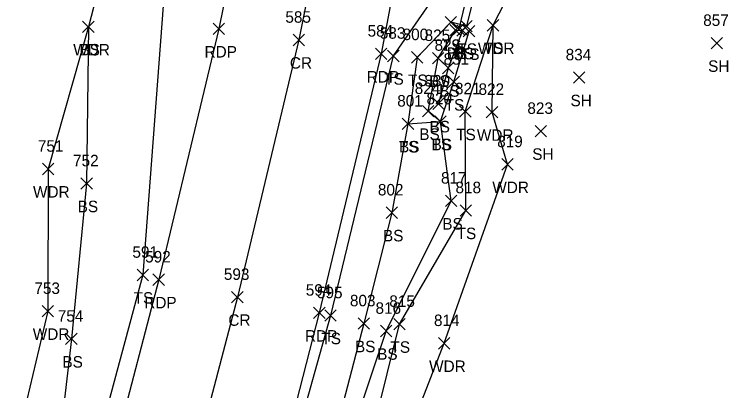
# Model space of a CAD drawing. Extents: x 1638705 to 1644019, y 630225 to 637423.
# Drawn here: x 1643815.9 to 1643939.5, y 636901.8 to 636967.4 of the extents above; entities that cross this region are included whole.
import ezdxf

# ---------------------------------------------------------------- set-up
doc = ezdxf.new("R2010")
doc.units = 0
for name, color, linetype in [('D_A', 7, 'Continuous'), ('D_TIC', 7, 'Continuous'), ('DCP', 7, 'Continuous'), ('L_A', 7, 'Continuous'), ('L_I', 7, 'Continuous'), ('L_TIC', 7, 'Continuous'), ('LAWA', 7, 'Continuous'), ('LELB', 7, 'Continuous'), ('P_A', 7, 'Continuous'), ('P_I', 7, 'Continuous'), ('P_TIC', 7, 'Continuous'), ('PET', 7, 'Continuous'), ('PRC', 7, 'Continuous')]:
    doc.layers.add(name, color=color, linetype=linetype)

msp = doc.modelspace()

# ---------------------------------------------------------------- linework, layer by layer
at = {"layer": 'D_TIC'}
for points in [[(1643892.43, 636963.79), (1643894.43, 636965.79)], [(1643894.43, 636963.79), (1643892.43, 636965.79)]]:
    msp.add_lwpolyline(points, dxfattribs=at)
at = {"layer": 'DCP'}
msp.add_lwpolyline([(1643899.78, 636991.21), (1643893.43, 636964.79)], dxfattribs=at)
at = {"layer": 'L_TIC'}
for points in [[(1643891.04, 636964.97), (1643893.04, 636966.97)], [(1643893.04, 636964.97), (1643891.04, 636966.97)], [(1643827.82, 636964.18), (1643829.82, 636966.18)], [(1643829.82, 636964.18), (1643827.82, 636966.18)], [(1643827.82, 636964.18), (1643829.82, 636966.18)], [(1643829.82, 636964.18), (1643827.82, 636966.18)], [(1643891.86, 636963.57), (1643893.86, 636965.57)], [(1643893.86, 636963.57), (1643891.86, 636965.57)], [(1643893.09, 636963.51), (1643895.09, 636965.51)], [(1643895.09, 636963.51), (1643893.09, 636965.51)], [(1643893.77, 636964.28), (1643895.77, 636966.28)], [(1643895.77, 636964.28), (1643893.77, 636966.28)], [(1643894.22, 636963.41), (1643896.22, 636965.41)], [(1643896.22, 636963.41), (1643894.22, 636965.41)], [(1643898.4, 636964.43), (1643900.4, 636966.43)], [(1643900.4, 636964.43), (1643898.4, 636966.43)], [(1643898.4, 636964.43), (1643900.4, 636966.43)], [(1643900.4, 636964.43), (1643898.4, 636966.43)], [(1643937.43, 636961.32), (1643939.43, 636963.32)], [(1643939.43, 636961.32), (1643937.43, 636963.32)], [(1643881.01, 636959.09), (1643883.01, 636961.09)], [(1643883.01, 636959.09), (1643881.01, 636961.09)], [(1643885.16, 636958.85), (1643887.16, 636960.85)], [(1643887.16, 636958.85), (1643885.16, 636960.85)], [(1643888.82, 636958.7), (1643890.82, 636960.7)], [(1643890.82, 636958.7), (1643888.82, 636960.7)], [(1643890.57, 636956.99), (1643892.57, 636958.99)], [(1643892.57, 636956.99), (1643890.57, 636958.99)], [(1643913.43, 636955.33), (1643915.43, 636957.33)], [(1643915.43, 636955.33), (1643913.43, 636957.33)], [(1643891.56, 636954.57), (1643893.56, 636956.57)], [(1643893.56, 636954.57), (1643891.56, 636956.57)], [(1643888.88, 636950.78), (1643890.88, 636952.78)], [(1643890.88, 636950.78), (1643888.88, 636952.78)], [(1643887.1, 636949.47), (1643889.1, 636951.47)], [(1643889.1, 636949.47), (1643887.1, 636951.47)], [(1643893.56, 636949.41), (1643895.56, 636951.41)], [(1643895.56, 636949.41), (1643893.56, 636951.41)], [(1643898.23, 636949.31), (1643900.23, 636951.31)], [(1643900.23, 636949.31), (1643898.23, 636951.31)], [(1643883.56, 636947.28), (1643885.56, 636949.28)], [(1643885.56, 636947.28), (1643883.56, 636949.28)], [(1643883.56, 636947.28), (1643885.56, 636949.28)], [(1643885.56, 636947.28), (1643883.56, 636949.28)], [(1643889.24, 636947.66), (1643891.24, 636949.66)], [(1643891.24, 636947.66), (1643889.24, 636949.66)], [(1643889.24, 636947.66), (1643891.24, 636949.66)], [(1643891.24, 636947.66), (1643889.24, 636949.66)], [(1643906.75, 636946), (1643908.75, 636948)], [(1643908.75, 636946), (1643906.75, 636948)], [(1643900.92, 636940.2), (1643902.92, 636942.2)], [(1643902.92, 636940.2), (1643900.92, 636942.2)], [(1643820.8, 636939.41), (1643822.8, 636941.41)], [(1643822.8, 636939.41), (1643820.8, 636941.41)], [(1643827.51, 636936.87), (1643829.51, 636938.87)], [(1643829.51, 636936.87), (1643827.51, 636938.87)], [(1643891.11, 636933.85), (1643893.11, 636935.85)], [(1643893.11, 636933.85), (1643891.11, 636935.85)], [(1643880.76, 636931.79), (1643882.76, 636933.79)], [(1643882.76, 636931.79), (1643880.76, 636933.79)], [(1643893.64, 636932.18), (1643895.64, 636934.18)], [(1643895.64, 636932.18), (1643893.64, 636934.18)], [(1643837.3, 636920.94), (1643839.3, 636922.94)], [(1643839.3, 636920.94), (1643837.3, 636922.94)], [(1643820.76, 636914.63), (1643822.76, 636916.63)], [(1643822.76, 636914.63), (1643820.76, 636916.63)], [(1643870.05, 636913.88), (1643872.05, 636915.88)], [(1643872.05, 636913.88), (1643870.05, 636915.88)], [(1643875.88, 636912.48), (1643877.88, 636914.48)], [(1643877.88, 636912.48), (1643875.88, 636914.48)], [(1643882.1, 636912.38), (1643884.1, 636914.38)], [(1643884.1, 636912.38), (1643882.1, 636914.38)], [(1643879.75, 636911.17), (1643881.75, 636913.17)], [(1643881.75, 636911.17), (1643879.75, 636913.17)], [(1643824.85, 636909.8), (1643826.85, 636911.8)], [(1643826.85, 636909.8), (1643824.85, 636911.8)], [(1643889.89, 636909.04), (1643891.89, 636911.04)], [(1643891.89, 636909.04), (1643889.89, 636911.04)]]:
    msp.add_lwpolyline(points, dxfattribs=at)
at = {"layer": 'LAWA'}
for points in [[(1643865.64, 637303.77), (1643862.82, 637270.27), (1643861.25, 637253.7), (1643870.99, 637241.9), (1643867.11, 637203.42), (1643864.21, 637161.34), (1643862.97, 637130.77), (1643854.22, 637098.04), (1643864.2, 637092.72), (1643858.24, 637074.74), (1643852.38, 637053.09), (1643849.03, 637029.11), (1643850.77, 637013.92), (1643837.37, 636980.48), (1643832.85, 636980.73), (1643828.82, 636965.18), (1643821.8, 636940.41), (1643821.76, 636915.63), (1643813.91, 636882.55), (1643810.67, 636866.31)], [(1643866.42, 636846.23), (1643870.33, 636868.74), (1643881.97, 636887.15), (1643890.89, 636910.04), (1643901.92, 636941.2), (1643899.23, 636950.31), (1643899.4, 636965.43), (1643906.72, 636979.6), (1643908.72, 636993.2), (1643928.1, 637008.65), (1643931.38, 637033.38), (1643927.97, 637042.71)]]:
    msp.add_lwpolyline(points, dxfattribs=at)
at = {"layer": 'LELB'}
for points in [[(1643917.29, 637304.48), (1643919.24, 637262.47), (1643916.89, 637218.55), (1643914.08, 637180.95), (1643910.3, 637135.87), (1643913.16, 637114.46), (1643911.21, 637098.67), (1643904.37, 637090.61), (1643898.51, 637049.58), (1643891.41, 637000.85), (1643892.59, 636975.41), (1643882.01, 636960.09), (1643871.05, 636914.88), (1643861.76, 636881.64), (1643855.17, 636855.93)], [(1643881.31, 637303.51), (1643880.47, 637260.36), (1643877.75, 637219.48), (1643872.16, 637183.49), (1643871.11, 637167.53), (1643875.06, 637139.18), (1643871.64, 637093.85), (1643865.67, 637053.39), (1643855.97, 637011.76), (1643842.4, 636975.8), (1643838.3, 636921.94), (1643830.67, 636893.45), (1643822.68, 636863.82)], [(1643913.32, 637074.89), (1643909.21, 637064.03), (1643906.43, 637047.21), (1643907.23, 637022.8), (1643903.37, 637008.28), (1643895.6, 636995.38), (1643898.69, 636989.86), (1643900.72, 636989.28), (1643894.77, 636965.28), (1643892.04, 636965.97), (1643886.16, 636959.85), (1643884.56, 636948.28), (1643890.24, 636948.66), (1643892.56, 636955.57), (1643895.22, 636964.41)], [(1643870.33, 636868.74), (1643876.6, 636887.17), (1643883.1, 636913.38), (1643894.64, 636933.18), (1643894.56, 636950.41), (1643899.4, 636965.43)], [(1643828.82, 636965.18), (1643828.51, 636937.87), (1643825.85, 636910.8), (1643822.97, 636885.89), (1643815.74, 636865.22)], [(1643860.83, 636847.55), (1643868.13, 636873.63), (1643872.66, 636888.12), (1643880.75, 636912.17), (1643892.11, 636934.85), (1643890.24, 636948.66), (1643888.1, 636950.47), (1643889.82, 636959.7), (1643892.86, 636964.57), (1643894.09, 636964.51), (1643891.57, 636957.99), (1643889.88, 636951.78)], [(1643884.56, 636948.28), (1643881.76, 636932.79), (1643876.88, 636913.48), (1643870.82, 636890.34), (1643863.68, 636867.43), (1643857.57, 636848.74)]]:
    msp.add_lwpolyline(points, dxfattribs=at)
at = {"layer": 'P_TIC'}
for points in [[(1643850.59, 636963.82), (1643852.59, 636965.82)], [(1643852.59, 636963.82), (1643850.59, 636965.82)], [(1643864.54, 636961.88), (1643866.54, 636963.88)], [(1643866.54, 636961.88), (1643864.54, 636963.88)], [(1643878.88, 636959.46), (1643880.88, 636961.46)], [(1643880.88, 636959.46), (1643878.88, 636961.46)], [(1643840.08, 636920.12), (1643842.08, 636922.12)], [(1643842.08, 636920.12), (1643840.08, 636922.12)], [(1643853.81, 636917.08), (1643855.81, 636919.08)], [(1643855.81, 636917.08), (1643853.81, 636919.08)], [(1643868.1, 636914.33), (1643870.1, 636916.33)], [(1643870.1, 636914.33), (1643868.1, 636916.33)]]:
    msp.add_lwpolyline(points, dxfattribs=at)
at = {"layer": 'PET'}
for points in [[(1643915.42, 637304.49), (1643914.6, 637262.42), (1643913.48, 637219.01), (1643911.31, 637181.13), (1643907.88, 637136.04), (1643902.19, 637091.19), (1643896.2, 637050.09), (1643887.54, 637001.12), (1643879.88, 636960.46), (1643869.1, 636915.33), (1643860.5, 636882.08), (1643852.88, 636856.28)], [(1643886.09, 637303.33), (1643885.33, 637260.95), (1643884.29, 637219.34), (1643882.65, 637181.95), (1643878.66, 637138.56), (1643873.79, 637093.66), (1643868.41, 637053.44), (1643859.66, 637004.66), (1643851.59, 636964.82), (1643841.08, 636921.12), (1643833.58, 636892.49), (1643824.77, 636863.46)]]:
    msp.add_lwpolyline(points, dxfattribs=at)
at = {"layer": 'PRC'}
msp.add_lwpolyline([(1643901.07, 637302.92), (1643900.04, 637261.19), (1643898.85, 637218.55), (1643896.7, 637181.82), (1643893.13, 637137.2), (1643887.51, 637091.29), (1643882.08, 637051.36), (1643873.69, 637003.61), (1643865.54, 636962.88), (1643854.81, 636918.08), (1643846.66, 636887.04), (1643838.69, 636859.97)], dxfattribs=at)

# ---------------------------------------------------------------- texts
at = {"layer": 'D_A'}
msp.add_text('P', height=2, dxfattribs=at).set_placement((1643892.8, 636959.79))
at = {"layer": 'L_A'}
for s, p in [('TS', (1643890.45, 636960.97)), ('WDR', (1643826.18, 636960.18)), ('BS', (1643827.26, 636960.18)), ('BS', (1643891.3, 636959.57)), ('BS', (1643892.53, 636959.51)), ('TS', (1643893.18, 636960.28)), ('WDR', (1643896.76, 636960.43)), ('TS', (1643897.81, 636960.43)), ('TS', (1643893.63, 636959.41)), ('SH', (1643936.92, 636957.32)), ('TS', (1643880.42, 636955.09)), ('TS', (1643884.57, 636954.85)), ('BS', (1643888.26, 636954.7)), ('BS', (1643890.01, 636952.99)), ('SH', (1643912.92, 636951.33)), ('TS', (1643890.97, 636950.57)), ('BS', (1643888.32, 636946.78)), ('BS', (1643886.54, 636945.47)), ('TS', (1643892.97, 636945.41)), ('WDR', (1643896.59, 636945.31)), ('TS', (1643888.65, 636943.66)), ('BS', (1643888.68, 636943.66)), ('TS', (1643882.97, 636943.28)), ('BS', (1643883, 636943.28)), ('SH', (1643906.24, 636942)), ('WDR', (1643899.28, 636936.2)), ('WDR', (1643819.16, 636935.41)), ('BS', (1643826.95, 636932.87)), ('BS', (1643890.55, 636929.85)), ('BS', (1643880.2, 636927.79)), ('TS', (1643893.05, 636928.18)), ('TS', (1643836.71, 636916.94)), ('WDR', (1643819.12, 636910.63)), ('TS', (1643869.46, 636909.88)), ('BS', (1643875.32, 636908.48)), ('TS', (1643881.51, 636908.38)), ('BS', (1643879.19, 636907.17)), ('BS', (1643824.29, 636905.8)), ('WDR', (1643888.25, 636905.04))]:
    msp.add_text(s, height=2, dxfattribs=at).set_placement(p)
at = {"layer": 'L_I'}
for s, p in [('857', (1643936.06, 636965.32)), ('583', (1643879.65, 636963.09)), ('800', (1643883.63, 636962.85)), ('825', (1643887.46, 636962.7)), ('829', (1643889.2, 636960.99)), ('831', (1643890.77, 636958.57)), ('834', (1643912.07, 636959.33)), ('830', (1643887.43, 636954.78)), ('824', (1643885.74, 636953.47)), ('821', (1643892.76, 636953.41)), ('822', (1643896.87, 636953.31)), ('801', (1643882.69, 636951.28)), ('801', (1643882.69, 636951.28)), ('820', (1643887.79, 636951.66)), ('820', (1643887.79, 636951.66)), ('823', (1643905.39, 636950)), ('819', (1643900.12, 636944.2)), ('751', (1643820.01, 636943.41)), ('752', (1643826.14, 636940.87)), ('817', (1643890.32, 636937.85)), ('818', (1643892.85, 636936.18)), ('802', (1643879.32, 636935.79)), ('591', (1643836.5, 636924.94)), ('753', (1643819.4, 636918.63)), ('595', (1643868.69, 636917.88)), ('803', (1643874.44, 636916.48)), ('815', (1643881.31, 636916.38)), ('816', (1643878.9, 636915.17)), ('754', (1643823.48, 636913.8)), ('814', (1643889.1, 636913.04))]:
    msp.add_text(s, height=2, dxfattribs=at).set_placement(p)
at = {"layer": 'P_A'}
for s, p in [('RDP', (1643849.08, 636959.82)), ('CR', (1643863.97, 636957.88)), ('RDP', (1643877.37, 636955.46)), ('RDP', (1643838.57, 636916.12)), ('CR', (1643853.24, 636913.08)), ('RDP', (1643866.59, 636910.33))]:
    msp.add_text(s, height=2, dxfattribs=at).set_placement(p)
at = {"layer": 'P_I'}
for s, p in [('585', (1643863.18, 636965.88)), ('584', (1643877.52, 636963.46)), ('592', (1643838.72, 636924.12)), ('593', (1643852.45, 636921.08)), ('594', (1643866.74, 636918.33))]:
    msp.add_text(s, height=2, dxfattribs=at).set_placement(p)

doc.saveas('drawing.dxf')
